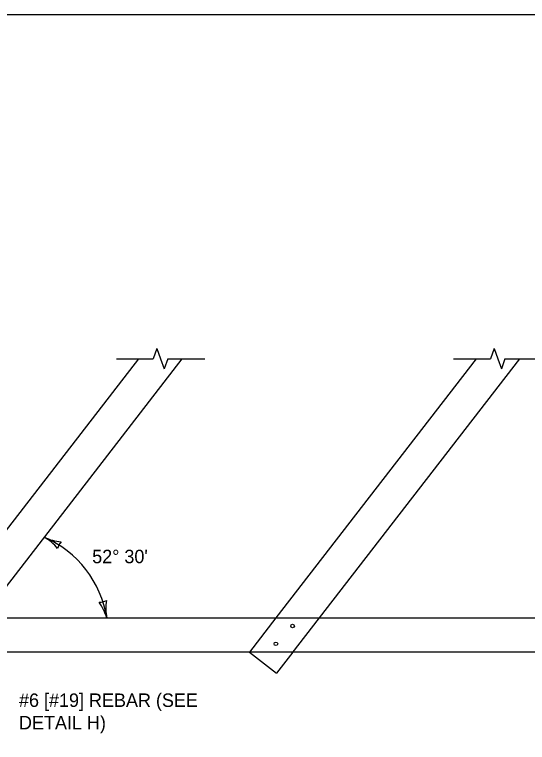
# Model space of a CAD drawing. Extents: x 49991.4 to 50021, y 49987.6 to 50011.4.
# Drawn here: x 50002.416 to 50004.704, y 49995.752 to 49998.999 of the extents above; entities that cross this region are included whole.
import ezdxf

# ---------------------------------------------------------------- set-up
doc = ezdxf.new("R2010")
doc.units = 0
for name, color, linetype in [('Level 1', 7, 'Continuous'), ('Level 2', 7, 'Continuous'), ('Level 3', 7, 'Continuous'), ('Level 4', 7, 'Continuous'), ('Level 6', 7, 'Continuous')]:
    doc.layers.add(name, color=color, linetype=linetype)

msp = doc.modelspace()

# ---------------------------------------------------------------- linework, layer by layer
at = {"layer": 'Level 1'}
for p, q in [((50002.0774, 49996.308), (50002.9709, 49997.464)), ((50002.2708, 49996.308), (50003.1643, 49997.464)), ((50004.4751, 49997.464), (50003.5819, 49996.308)), ((50004.6684, 49997.464), (50003.7753, 49996.308)), ((50002.1929, 49996.308), (50004.9173, 49996.308)), ((50004.9173, 49996.155), (50002.0729, 49996.155)), ((50003.4637, 49996.155), (50003.5848, 49996.0614)), ((50003.6571, 49996.155), (50003.5848, 49996.0614))]:
    msp.add_line(p, q, dxfattribs=at)
msp.add_lwpolyline([(49999.3835, 49998.9992), (50016.7501, 49998.9992), (50016.7501, 49987.7988), (49999.3835, 49987.7988)], close=True, dxfattribs=at)
for centre in [(50003.6565, 49996.2716), (50003.5821, 49996.1922)]:
    msp.add_circle(centre, 0.00797, dxfattribs=at)
at = {"layer": 'Level 3'}
for centre, radius, start, end in [((50002.362, 49996.2353), 0.4709, 8.8781, 66.6347), ((50002.4369, 49996.4755), 0.2223, 39.6007, 59.7842), ((50002.6473, 49996.8787), 0.233, 244.972, 264.2218), ((50002.6621, 49996.6077), 0.0548, 134.2835, 170.0058), ((50002.7974, 49996.4327), 0.0548, 265.6071, 301.3295), ((50002.6036, 49996.2426), 0.233, 16.2956, 35.5455), ((50003.0454, 49996.3508), 0.2223, 170.9243, 191.1078)]:
    msp.add_arc(centre, radius, start, end, dxfattribs=at)
at = {"layer": 'Level 4'}
for p, q in [((50003.5819, 49996.308), (50003.4637, 49996.155)), ((50003.7753, 49996.308), (50003.6537, 49996.1506))]:
    msp.add_line(p, q, dxfattribs=at)
at = {"layer": 'Level 6'}
for p, q in [((50003.0514, 49997.5097), (50003.0352, 49997.464)), ((50003.0514, 49997.5097), (50003.0676, 49997.464)), ((50004.5555, 49997.5097), (50004.5393, 49997.464)), ((50004.5555, 49997.5097), (50004.5717, 49997.464)), ((50002.8709, 49997.464), (50003.0352, 49997.464)), ((50003.0676, 49997.464), (50003.0838, 49997.4183)), ((50003.1, 49997.464), (50003.0838, 49997.4183)), ((50003.1, 49997.464), (50003.2643, 49997.464)), ((50004.3751, 49997.464), (50004.5393, 49997.464)), ((50004.5717, 49997.464), (50004.5879, 49997.4183)), ((50004.6041, 49997.464), (50004.5879, 49997.4183)), ((50004.6041, 49997.464), (50004.8133, 49997.464))]:
    msp.add_line(p, q, dxfattribs=at)

# ---------------------------------------------------------------- texts
at = {"layer": 'Level 2'}
for s, p in [("52° 30'", (50002.7625, 49996.552)), ('#6 [#19] REBAR (SEE', (50002.4359, 49995.9108)), ('DETAIL H)', (50002.4359, 49995.8108))]:
    msp.add_text(s, height=0.06, dxfattribs=at).set_placement(p)

doc.saveas('drawing.dxf')
